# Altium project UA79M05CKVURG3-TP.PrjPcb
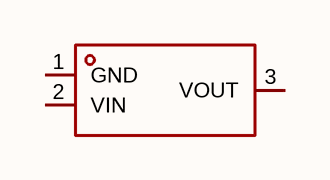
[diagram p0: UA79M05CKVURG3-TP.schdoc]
1 sheet, 1 parts. Net scope: global (net labels, ports and power ports of the same name join across sheets).

## Sheet UA79M05CKVURG3-TP.schdoc
size 127 x 101 mm

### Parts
U?  ua79m05ckvurg3-tp  [TO-252-2_L6.6-W6.1-P4.57-LS10.0-BR-CW]  (value not drawn)

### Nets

Not connected (* = marked no-connect by the designer): U? 1(GND) 2(VIN) 3(VOUT)

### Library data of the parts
U? = ua79m05ckvurg3-tp: 输出极性:负极;工作电压:-;输出电压:5V;输出电流:500mA;电源纹波抑制比(PSRR):-;输出类型:固定;; Manufacturer: TECH PUBLIC(台舟); AddInBom: yes; ModelId: 16697a7febd74ea38893a430a7be29f0; ModelTransform: 393.7,259.842,0,0,0,0,-34.45,-0.005,0; Output Configuration: 负极; Output Voltage: 5V; Output Current: 500mA; Voltage Dropout: 2V@(350mA); standby current: 1.5mA; Noise: 200uV; Output Type: 固定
